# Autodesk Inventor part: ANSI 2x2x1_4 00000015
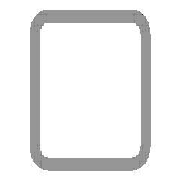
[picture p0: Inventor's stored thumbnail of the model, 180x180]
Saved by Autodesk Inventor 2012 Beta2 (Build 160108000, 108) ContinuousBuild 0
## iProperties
IsCustomPart: 1
Created: 2011-01
Part Number: ANSI 2x2x1_4 00000015
Material: Steel, Mild
Description: Tube
Document SubType Name: Modeling
Standard: ANSI
Designer: Beta-8540w
Standards Organization: ANSI
Language: en-US
Size Designation: 3x3x3/16
Categories: <MemberInstance><Categories><Category DisplayName="Structural Shapes" InternalName="089c4875-fa83-4c05-b084-43b9cc11f5ed" Mnemonic="GRDR"><CategoryParameter Dis
Stock Number: 3x3x3/16
Density: 7.86 g/cm^3
_CCFamilyMember: 9
_CCFamilyDisplayName: ANSI AISC (Square) - Tube
_FrameMemberDoc: Frame Member File
_Version: 15.0.0
_GetPNFromCC: 1
G_L: 48.000 in
G_W: 3.000 in
G_H: 3.000 in
Author: Beta-8540w
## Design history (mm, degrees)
node "Start plane"
node "End plane"
sketch "Sketch"
  geometry: L1 (-38.1, -28.575)-(-38.1, 28.575); L2 (-28.575, 38.1)-(28.575, 38.1); L3 (38.1, 28.575)-(38.1, -28.575); L4 (28.575, -38.1)-(-28.575, -38.1); L5 (-28.575, 33.337)-(28.575, 33.338); L6 (33.338, 28.575)-(33.338, -28.575); L7 (28.575, -33.337)-(-28.575, -33.338); L8 (-33.338, -28.575)-(-33.338, 28.575); L9 (0, 56.102)-(0, -56.102) reference; L10 (-56.102, 0)-(56.102, 0) reference; A1 r 9.525 centre (-28.575, -28.575) between (-38.1, -28.575) and (-28.575, -38.1); A2 r 9.525 centre (-28.575, 28.575) between (-28.575, 38.1) and (-38.1, 28.575); A3 r 9.525 centre (28.575, 28.575) between (38.1, 28.575) and (28.575, 38.1); A4 r 9.525 centre (28.575, -28.575) between (28.575, -38.1) and (38.1, -28.575); A5 r 4.763 centre (-28.575, 28.575) between (-28.575, 33.337) and (-33.338, 28.575); A6 r 4.763 centre (28.575, 28.575) between (33.338, 28.575) and (28.575, 33.338); A7 r 4.763 centre (28.575, -28.575) between (28.575, -33.337) and (33.338, -28.575); A8 r 4.763 centre (-28.575, -28.575) between (-33.338, -28.575) and (-28.575, -33.338)
  constraints: 16 end point, 16 point on circle, 8 centre point, 8 tangent, 4 parallel, 3 equal radius, 2 perpendicular, 7 other
  dimensions: "d10" = 76.2 distance between parallel lines of L2 L4 (= G_H); "d11" = 76.2 distance between parallel lines of L1 L3 (= G_W); "d12" = 4.7625 distance between parallel lines of L3 L6 (= G_T); "d15" = 38.1 distance between parallel lines of L2 L10 (= 0.5 x d10); "d16" = 38.1 distance between parallel lines of L9 L3 (= 0.5 x d11); "d17" = 9.525 radius of A1 (= G_IR)
extrude "Body" new body sketch "Sketch" stored distance "d3" = 1219.2 (= G_L); taper "d4" = 0 deg
node "Driven Length"
  sketch "Sketch3"
    geometry: L1 (0, 0)-(10, 0) reference
    constraints: 2 end point, 1 horizontal
  workplane "Work Plane3"
  sketch "Sketch4"
    geometry: L1 (-2, 0)-(12, 0) reference; L2 (-2, 1219.2)-(12, 1219.2) reference
    dimensions: "d19" = 1219.2 distance between parallel lines of L1 L2 (derived)
body "Solid1"
other parameters: "G_W" = 76.2 [user parameter; used in 1 equation term], "G_H" = 76.2 [user parameter; used in 1 equation term], "G_T" = 4.7625 [user parameter; used in 1 equation term], "G_IR" = 9.525 [user parameter; used in 1 equation term], "G_L" = 1219.2 (= d19) [user parameter; used in 1 equation term], "G_OFFSET_START" = 0 [user parameter; used in 1 equation term], "G_OFFSET_END" = 0 [user parameter; used in 1 equation term], "d13" = 0 (computed from G_OFFSET_START), "d14" = 1219.2 (= G_OFFSET_END + B_L), "B_L" = 1219.2 [user parameter; used in 1 equation term], "d18" = 90 deg
